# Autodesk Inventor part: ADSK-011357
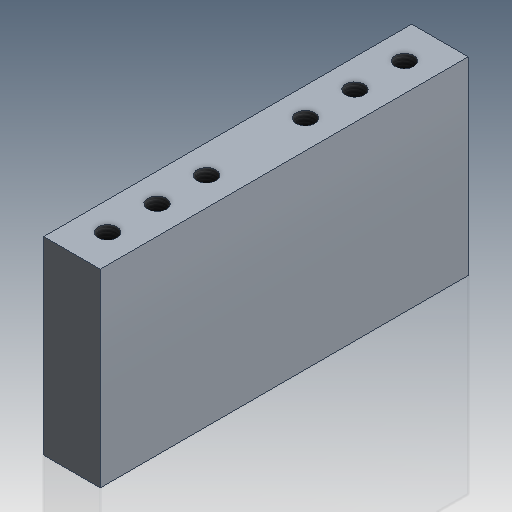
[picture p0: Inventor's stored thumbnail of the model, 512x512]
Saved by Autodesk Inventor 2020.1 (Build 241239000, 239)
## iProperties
Created: 1999-12
Part Number: ADSK-011357
Material: Pearson Aluminium
Description: PLT-09,FA,CP,07,026,051,BLOCK,MNT,TIMING_BELT
Document SubType Name: Modeling
Designer: sspink
Density: 2.71 g/cm^3
Appearance: Pearson-Aluminum
Mass: 453.365 g
Surface Area: 295.547 cm^2
Volume: 167.293 cm^3
Control State: 0
Checked Out: False
Master: False
Shininess: 35.0
Length Units: 11269
Angle Units: 11279
Time Units: 11290
Mass Units: 11283
Length Display Precision: 3
Angle Display Precision: 2
Compacted: True
Dimensions: 20x67x130,2 mm
Mass: 0,453 kg
DocNumber: ADSK-011357.ipt
Folder: 01 - Themengebiete\Simplification\01 - Packaging machine\
VDS_Category: 3D Komponenten
Density: 2.71
Volumn: 154.09010176277914
Area: 305.3057301923691
PropertySet Name: Model Information
Author: sspink
Revision Number: -
Title: PLT-09,FA,CP,07,026,051,BLOCK,MNT,TIMING_BELT
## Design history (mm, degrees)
node "Solide1"
  node "Extrusion1" dims "d4" = 130.175, "d5" = 0
  node "Hole1" dims "d10" = 6.647, "d11" = 9.525, "d12" = 6.35, "d13" = 60 deg, "d14" = 22.2, "d15" = 118 deg, "d38" = 16
  node "Hole2" dims "d22" = 6.647, "d23" = 9.525, "d24" = 6.35, "d25" = 60 deg, "d26" = 22.2, "d27" = 118 deg, "d42" = 16
  node "Hole3" dims "d31" = 6.647, "d32" = 9.525, "d33" = 6.35, "d34" = 60 deg, "d35" = 22.2, "d36" = 118 deg, "d44" = 16
sketch "Sketch1"
  geometry: L1 (-10, -33.5)-(10, -33.5); L2 (10, -33.5)-(10, 33.5); L3 (10, 33.5)-(-10, 33.5); L4 (-10, 33.5)-(-10, -33.5); 3 further points
  constraints: 8 end point, 2 midpoint, 2 parallel, 1 horizontal, 1 horizontal alignment, 1 perpendicular, 1 vertical alignment
  dimensions: "d0" = 20 distance between parallel lines of L2 L4; "d3" = 67 distance of L1.end L2.end
sketch "Sketch2"
  geometry: L1 (0, 0)-(0, 130.175) reference; L2 (0, 0)-(20, 0) reference; L3 (10, 111.088)-(10, 19.087); 4 further points
  constraints: 3 midpoint, 3 vertical alignment, 2 end point, 1 coincident, 1 horizontal alignment, 1 vertical
  dimensions: "d37" = 92 distance of L3.end L3.start
sketch "Sketch3"
  geometry: L1 (20, 0)-(0, 0) reference; L2 (0, 0)-(0, -130.175) reference; L3 (10, -12.588)-(10, -117.587); L4 (20, 0)-(20, -130.175) reference; 5 further points
  constraints: 4 vertical alignment, 3 midpoint, 2 end point, 1 horizontal alignment, 1 parallel
  dimensions: "d39" = 105 distance of L3.start L3.end; "d40" = 35 distance of L3.start point (10, -47.588) (= 0.333333 x d39); "d41" = 35 distance of L3.end point (10, -82.587) (= 0.333333 x d39)
sketch "Sketch4"
  geometry: L1 (20, 0)-(0, 0) reference; L2 (0, 0)-(0, -130.175) reference; L3 (10, -30.088)-(10, -100.087); 3 further points
  constraints: 3 midpoint, 2 end point, 2 vertical alignment, 1 horizontal alignment, 1 parallel
  dimensions: "d43" = 70 distance of L3.end L3.start
node "Corps solides"
node "Corps surfaciques"
